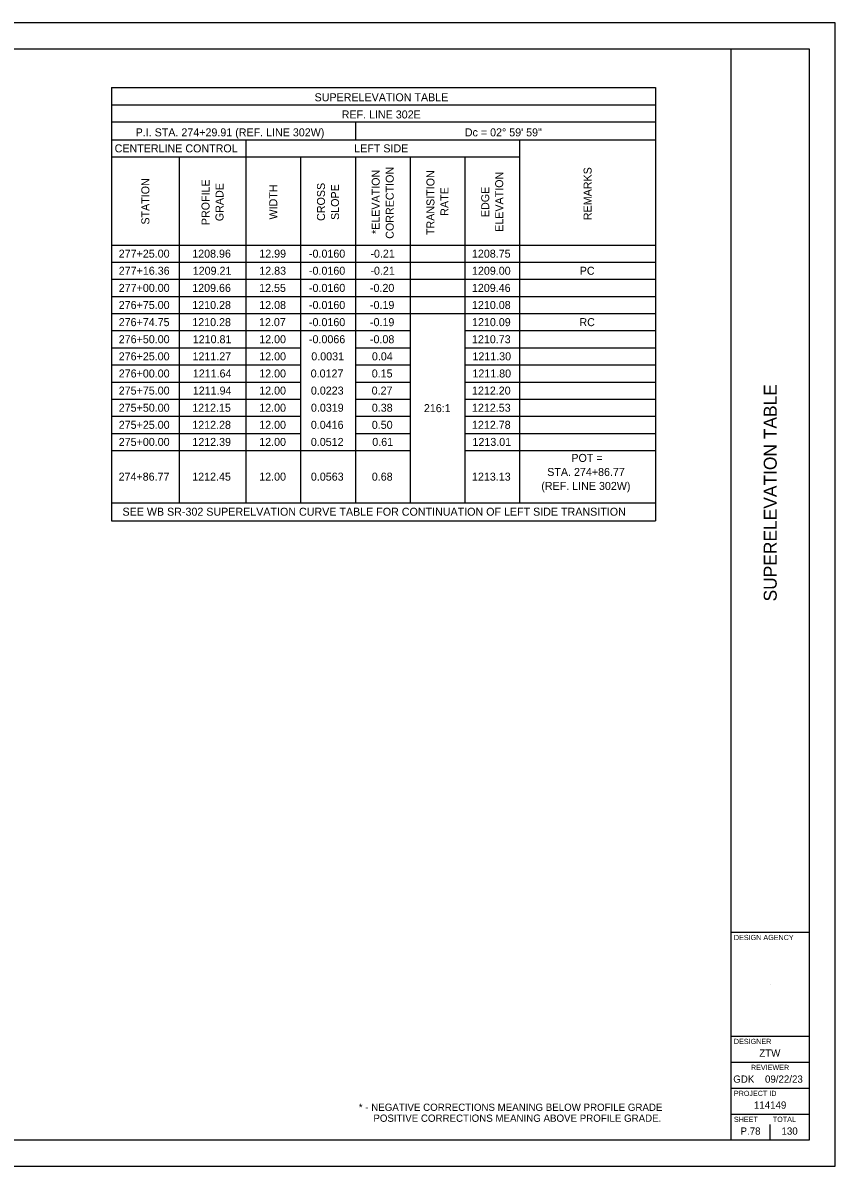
# Model space of a CAD drawing. Extents: x 0 to 34, y -1.2 to 22.
# Drawn here: x 18.36 to 34, y 0 to 22 of the extents above; entities that cross this region are included whole.
import ezdxf

# ---------------------------------------------------------------- set-up
doc = ezdxf.new("R2010")
doc.units = 0
for name, color, linetype in [('SH_Border', 7, 'Continuous'), ('SH_Cut_Line', 7, 'Continuous'), ('SH_Data', 7, 'Continuous'), ('SH_Text', 7, 'Continuous')]:
    doc.layers.add(name, color=color, linetype=linetype)

msp = doc.modelspace()

# ---------------------------------------------------------------- linework, layer by layer
at = {"layer": 'SH_Border'}
for p, q in [((32, 0.5), (32, 21.5)), ((32, 4.5), (33.5, 4.5)), ((32, 2.5), (33.5, 2.5)), ((32, 2), (33.5, 2)), ((32, 1.5), (33.5, 1.5)), ((32, 1), (33.5, 1))]:
    msp.add_line(p, q, dxfattribs=at)
msp.add_lwpolyline([(1.5, 21.5), (33.5, 21.5), (33.5, 0.5), (1.5, 0.5)], close=True, dxfattribs=at)
at = {"layer": 'SH_Cut_Line'}
msp.add_lwpolyline([(0, 0), (34, 0), (34, 22), (0, 22)], close=True, dxfattribs=at)
at = {"layer": 'SH_Data'}
for p, q in [((32.75, 3.5), (32.75, 3.5)), ((32.375, 0.675), (32.375, 0.675)), ((32.75, 0.5), (32.75, 0.8))]:
    msp.add_line(p, q, dxfattribs=at)
at = {"layer": 'SH_Text'}
for p, q in [((20.067, 20.754), (30.542, 20.754)), ((20.067, 20.754), (20.067, 12.42)), ((30.542, 20.754), (30.542, 12.42)), ((20.067, 20.425), (30.542, 20.425)), ((20.067, 20.096), (30.542, 20.096)), ((24.761, 20.096), (24.761, 19.75)), ((20.067, 19.75), (30.542, 19.75)), ((22.653, 19.75), (22.653, 12.766)), ((27.923, 19.75), (27.923, 12.766)), ((20.067, 19.42), (27.923, 19.42)), ((21.368, 19.42), (21.368, 12.766)), ((23.707, 19.42), (23.707, 12.766)), ((24.761, 19.42), (24.761, 12.766)), ((25.815, 19.42), (25.815, 12.766)), ((26.869, 19.42), (26.869, 12.766)), ((20.067, 17.724), (30.542, 17.724)), ((20.067, 17.394), (30.542, 17.394)), ((20.067, 17.065), (30.542, 17.065)), ((20.067, 16.736), (30.542, 16.736)), ((20.067, 16.406), (30.542, 16.406)), ((20.067, 16.077), (25.815, 16.077)), ((26.869, 16.077), (30.542, 16.077)), ((20.067, 15.747), (23.707, 15.747)), ((24.761, 15.747), (25.815, 15.747)), ((26.869, 15.747), (30.542, 15.747)), ((20.067, 15.418), (23.707, 15.418)), ((24.761, 15.418), (25.815, 15.418)), ((26.869, 15.418), (30.542, 15.418)), ((20.067, 15.088), (23.707, 15.088)), ((24.761, 15.088), (25.815, 15.088)), ((26.869, 15.088), (30.542, 15.088)), ((20.067, 14.759), (23.707, 14.759)), ((24.761, 14.759), (25.815, 14.759)), ((26.869, 14.759), (30.542, 14.759)), ((20.067, 14.43), (23.707, 14.43)), ((24.761, 14.43), (25.815, 14.43)), ((26.869, 14.43), (30.542, 14.43)), ((20.067, 14.1), (23.707, 14.1)), ((24.761, 14.1), (25.815, 14.1)), ((26.869, 14.1), (30.542, 14.1)), ((20.067, 13.771), (25.815, 13.771)), ((26.869, 13.771), (30.542, 13.771)), ((20.067, 12.766), (30.542, 12.766)), ((20.067, 12.42), (30.542, 12.42))]:
    msp.add_line(p, q, dxfattribs=at)

# ---------------------------------------------------------------- texts
at = {"layer": 'SH_Data'}
msp.add_text('SUPERELEVATION TABLE', height=0.25, rotation=90, dxfattribs=at).set_placement((32.875, 10.867))
for s, height, p in [('DESIGN AGENCY', 0.1, (32.05, 4.35)), ('DESIGNER', 0.1, (32.05, 2.35)), ('ZTW', 0.14, (32.539, 2.105)), ('REVIEWER', 0.1, (32.378, 1.85)), ('GDK', 0.14, (32.038, 1.605)), ('09/22/23', 0.14, (32.649, 1.605)), ('PROJECT ID', 0.1, (32.05, 1.35)), ('114149', 0.14, (32.435, 1.105)), ('SHEET', 0.1, (32.05, 0.85)), ('TOTAL', 0.1, (32.8, 0.85)), ('P.78', 0.14, (32.178, 0.605)), ('130', 0.14, (32.967, 0.605))]:
    msp.add_text(s, height=height, dxfattribs=at).set_placement(p)
at = {"layer": 'SH_Text'}
for s, height, p in [('SUPERELEVATION TABLE', 0.154, (23.976, 20.491)), ('REF. LINE 302E', 0.154, (24.498, 20.161)), ('P.I. STA. 274+29.91 (REF. LINE 302W)', 0.154, (20.53, 19.816)), ('Dc = 02° 59\' 59"', 0.154, (26.869, 19.816)), ('CENTERLINE CONTROL', 0.154, (20.126, 19.508)), ('LEFT SIDE', 0.154, (24.739, 19.508)), ('277+25.00', 0.154, (20.205, 17.482)), ('1208.96', 0.154, (21.62, 17.482)), ('12.99', 0.154, (22.911, 17.482)), ('-0.0160', 0.154, (23.868, 17.482)), ('-0.21', 0.154, (25.051, 17.482)), ('1208.75', 0.154, (27.006, 17.482)), ('277+16.36', 0.154, (20.205, 17.153)), ('1209.21', 0.154, (21.63, 17.153)), ('12.83', 0.154, (22.911, 17.153)), ('-0.0160', 0.154, (23.868, 17.153)), ('-0.21', 0.154, (25.051, 17.153)), ('1209.00', 0.154, (27.007, 17.153)), ('PC', 0.154, (29.082, 17.153)), ('277+00.00', 0.154, (20.205, 16.823)), ('1209.66', 0.154, (21.62, 16.823)), ('12.55', 0.154, (22.909, 16.823)), ('-0.0160', 0.154, (23.868, 16.823)), ('-0.20', 0.154, (25.042, 16.823)), ('1209.46', 0.154, (27.006, 16.823)), ('276+75.00', 0.154, (20.205, 16.494)), ('1210.28', 0.154, (21.621, 16.494)), ('12.08', 0.154, (22.91, 16.494)), ('-0.0160', 0.154, (23.868, 16.494)), ('-0.19', 0.154, (25.043, 16.494)), ('1210.08', 0.154, (27.007, 16.494)), ('276+74.75', 0.154, (20.204, 16.164)), ('1210.28', 0.154, (21.621, 16.164)), ('12.07', 0.154, (22.906, 16.164)), ('-0.0160', 0.154, (23.868, 16.164)), ('-0.19', 0.154, (25.043, 16.164)), ('1210.09', 0.154, (27.008, 16.164)), ('RC', 0.154, (29.076, 16.164)), ('276+50.00', 0.154, (20.205, 15.835)), ('1210.81', 0.154, (21.63, 15.835)), ('12.00', 0.154, (22.91, 15.835)), ('-0.0066', 0.154, (23.868, 15.835)), ('-0.08', 0.154, (25.042, 15.835)), ('1210.73', 0.154, (27.007, 15.835)), ('276+25.00', 0.154, (20.205, 15.506)), ('1211.27', 0.154, (21.625, 15.506)), ('12.00', 0.154, (22.91, 15.506)), ('0.0031', 0.154, (23.913, 15.506)), ('0.04', 0.154, (25.08, 15.506)), ('1211.30', 0.154, (27.015, 15.506)), ('276+00.00', 0.154, (20.205, 15.176)), ('1211.64', 0.154, (21.631, 15.176)), ('12.00', 0.154, (22.91, 15.176)), ('0.0127', 0.154, (23.901, 15.176)), ('0.15', 0.154, (25.077, 15.176)), ('1211.80', 0.154, (27.015, 15.176)), ('275+75.00', 0.154, (20.205, 14.847)), ('1211.94', 0.154, (21.631, 14.847)), ('12.00', 0.154, (22.91, 14.847)), ('0.0223', 0.154, (23.905, 14.847)), ('0.27', 0.154, (25.075, 14.847)), ('1212.20', 0.154, (27.007, 14.847)), ('275+50.00', 0.154, (20.205, 14.517)), ('1212.15', 0.154, (21.62, 14.517)), ('12.00', 0.154, (22.91, 14.517)), ('0.0319', 0.154, (23.906, 14.517)), ('0.38', 0.154, (25.078, 14.517)), ('216:1', 0.154, (26.081, 14.509)), ('1212.53', 0.154, (27.007, 14.517)), ('275+25.00', 0.154, (20.205, 14.188)), ('1212.28', 0.154, (21.621, 14.188)), ('12.00', 0.154, (22.91, 14.188)), ('0.0416', 0.154, (23.904, 14.188)), ('0.50', 0.154, (25.078, 14.188)), ('1212.78', 0.154, (27.007, 14.188)), ('275+00.00', 0.154, (20.205, 13.859)), ('1212.39', 0.154, (21.622, 13.859)), ('12.00', 0.154, (22.91, 13.859)), ('0.0512', 0.154, (23.904, 13.859)), ('0.61', 0.154, (25.087, 13.859)), ('1213.01', 0.154, (27.016, 13.859)), ('POT = ', 0.154, (28.921, 13.551)), ('STA. 274+86.77', 0.154, (28.456, 13.281)), ('274+86.77', 0.154, (20.202, 13.191)), ('1212.45', 0.154, (21.62, 13.191)), ('12.00', 0.154, (22.91, 13.191)), ('0.0563', 0.154, (23.905, 13.191)), ('0.68', 0.154, (25.078, 13.191)), ('1213.13', 0.154, (27.007, 13.191)), ('(REF. LINE 302W)', 0.154, (28.342, 13.012)), ('SEE WB SR-302 SUPERELVATION CURVE TABLE FOR CONTINUATION OF LEFT SIDE TRANSITION', 0.154, (20.277, 12.516)), ('* - NEGATIVE CORRECTIONS MEANING BELOW PROFILE GRADE', 0.14, (24.828, 1.063)), ('POSITIVE CORRECTIONS MEANING ABOVE PROFILE GRADE.', 0.14, (25.108, 0.853))]:
    msp.add_text(s, height=height, dxfattribs=at).set_placement(p)
for s, p in [('*ELEVATION ', (25.23, 17.937)), ('CORRECTION', (25.5, 17.845)), ('TRANSITION ', (26.284, 17.917)), ('REMARKS', (29.31, 18.204)), ('STATION', (20.794, 18.118)), ('PROFILE ', (21.953, 18.107)), ('ELEVATION', (27.608, 17.979)), ('GRADE', (22.222, 18.184)), ('WIDTH', (23.257, 18.216)), ('CROSS ', (24.176, 18.189)), ('SLOPE', (24.446, 18.208)), ('RATE', (26.554, 18.288)), ('EDGE ', (27.339, 18.262))]:
    msp.add_text(s, height=0.154, rotation=90, dxfattribs=at).set_placement(p)

doc.saveas('drawing.dxf')
